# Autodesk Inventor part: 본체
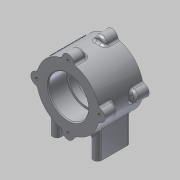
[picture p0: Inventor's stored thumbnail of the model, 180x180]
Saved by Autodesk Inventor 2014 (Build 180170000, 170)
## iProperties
Created: 2015-03
Part Number: 본체
Material: 알루미늄 6061
Document SubType Name: Modeling
Designer: MYHOME
Density: 2.71 g/cm^3
Appearance: 알루미늄 - 평지
Mass: 450.57 g
Surface Area: 333.077 cm^2
Volume: 166.262 cm^3
Author: MYHOME
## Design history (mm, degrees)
sketch "스케치1"
  geometry: C1 r 37 at (0, 0); 1 further point
  constraints: 1 centre point, 1 coincident
  dimensions: "d0" = 74 diameter of C1
extrude "돌출1" new body sketch "스케치1" distance "d1" = 52; taper "d2" = 0 deg
sketch "스케치2"
  geometry: C1 r 7 at (0, 37); C2 r 7 at (-37, 0); C3 r 7 at (0, -37); C4 r 7 at (37, 0); A1 r 37 centre (0, 0) between (0, 37) and (-37, 0) reference
  constraints: 4 centre point, 4 point on circle, 3 equal radius, 2 horizontal alignment, 2 vertical alignment
  dimensions: "d3" = 7 radius of C1
extrude "돌출2" join sketch "스케치2" distance "d4" = 15; taper "d5" = 0 deg
sketch "스케치3"
  geometry: A1 r 7 centre (0, 37) between (6.969, 36.338) and (-6.969, 36.338) reference; A2 r 7 centre (-37, 0) between (-36.338, 6.969) and (-36.338, -6.969) reference; A3 r 7 centre (0, -37) between (-6.969, -36.338) and (6.969, -36.338) reference; A4 r 7 centre (37, 0) between (36.338, -6.969) and (36.338, 6.969) reference; 4 further points
  constraints: 4 coincident
hole "구멍1" sketch "스케치3" at (0, 37), (-37, 0), (0, -37), (37, 0) diameter "d6" = 3.242; stored, may be unused: countersink angle "d10" = 90 deg, drill point angle "d12" = 118 deg; dims "d7" = 8, "d8" = 4, "d9" = 2, "d11" = 11
hole "구멍2" diameter "d15" = 42; stored, may be unused: countersink angle "d19" = 90 deg, drill point angle "d21" = 0 deg; dims "d16" = 8, "d17" = 47, "d18" = 22, "d20" = 30, "d31" = 10, "d32" = 10
hole "구멍3" diameter "d24" = 47; stored, may be unused: countersink angle "d28" = 90 deg, drill point angle "d30" = 0 deg; dims "d22" = 10, "d23" = 10, "d25" = 8, "d26" = 47, "d27" = 22, "d29" = 22
node "작업 평면1"
chamfer "모따기1" distance "d34" = 1; stored, may be unused: second distance "d35" = 2, angle "d36" = 45 deg
fillet "모깎기1" dims "d37" = 0.3
sketch "스케치4"
  geometry: L1 (0, 0)-(-21, 0); L2 (0, 0)-(-26.163, 26.163); A1 r 37 centre (0, 0) between (-6.969, 36.338) and (-36.338, 6.969) reference; 2 further points
  constraints: 4 end point, 1 coincident, 1 horizontal, 1 horizontal alignment, 1 point on circle, 1 other
  dimensions: "d38" = 45 deg angle of L1 L2
node "작업 평면2"
sketch "스케치5"
  geometry: L1 (20.767, 26)-(-20.767, 26) reference; L2 (-20.767, -26)-(20.767, -26) reference; 3 further points
  constraints: 1 midpoint, 1 vertical alignment, 1 other
  dimensions: "d39" = 26 distance from line of L1 point (0, 0)
feature "엠보싱1" sketch "스케치5" dims "d9" = 2, "d40" = 0.5, "d41" = 0
fillet "모깎기2" dims "d42" = 3
fillet "모깎기3" dims "d43" = 3
node "작업 평면3"
sketch "스케치6"
  geometry: L1 (-24, 46)-(-24, 6); L2 (-29, 41)-(-29, 11); L3 (-19, 11)-(-19, 41); L4 (24, 46)-(24, 6); L5 (29, 41)-(29, 11); L6 (19, 11)-(19, 41); L7 (-6.889, 52)-(6.889, 52) reference; L8 (-6.889, 0)-(6.889, 0) reference; L9 (9.104, 0)-(35.863, 0) reference; L10 (-35.863, 0)-(-9.104, 0) reference; L11 (-9.104, 52)-(-35.863, 52) reference; L12 (35.863, 52)-(9.104, 52) reference; L13 (37, 18)-(37, 34) reference; L14 (-37, 18)-(-37, 34) reference; L15 (0, 52)-(0, 0); L16 (0, 26)-(-32.045, 26); A1 r 5 centre (-24, 41) between (-19, 41) and (-29, 41); A2 r 5 centre (-24, 11) between (-29, 11) and (-19, 11); A3 r 5 centre (24, 41) between (29, 41) and (19, 41); A4 r 5 centre (24, 11) between (19, 11) and (29, 11); 2 further points
  constraints: 20 end point, 12 point on circle, 8 tangent, 4 centre point, 4 midpoint, 4 parallel, 4 point on line, 2 horizontal alignment, 1 perpendicular, 1 vertical
  dimensions: "d45" = 10 distance between parallel lines of L3 L2; "d46" = 10 distance between parallel lines of L5 L6; "d47" = 40 distance of L1.end L1.start; "d48" = 40 distance of L4.end L4.start; "d49" = 48 distance of point (24, 26) point (-24, 26); "d50" = 24 distance from line of L15 point (-24, 26)
extrude "돌출3" join sketch "스케치6" stored distance "d51" = 15; taper "d52" = 0 deg
fillet "모깎기4" dims "d53" = 3
sketch "스케치7"
  geometry: A1 r 5 centre (-24, 11) between (-29, 11) and (-19, 11) reference; A2 r 5 centre (-24, 41) between (-19, 41) and (-29, 41) reference; 3 further points
  constraints: 2 coincident
hole "구멍4" sketch "스케치7" at (-24, 41), (-24, 11) diameter "d54" = 4.459; stored, may be unused: countersink angle "d58" = 90 deg, drill point angle "d60" = 118 deg; dims "d55" = 6, "d56" = 47, "d57" = 22, "d59" = 8
node "솔리드1"
mirror "대칭1"
mirror "대칭2"
other parameters: "d33" = 26, "d44" = -56
